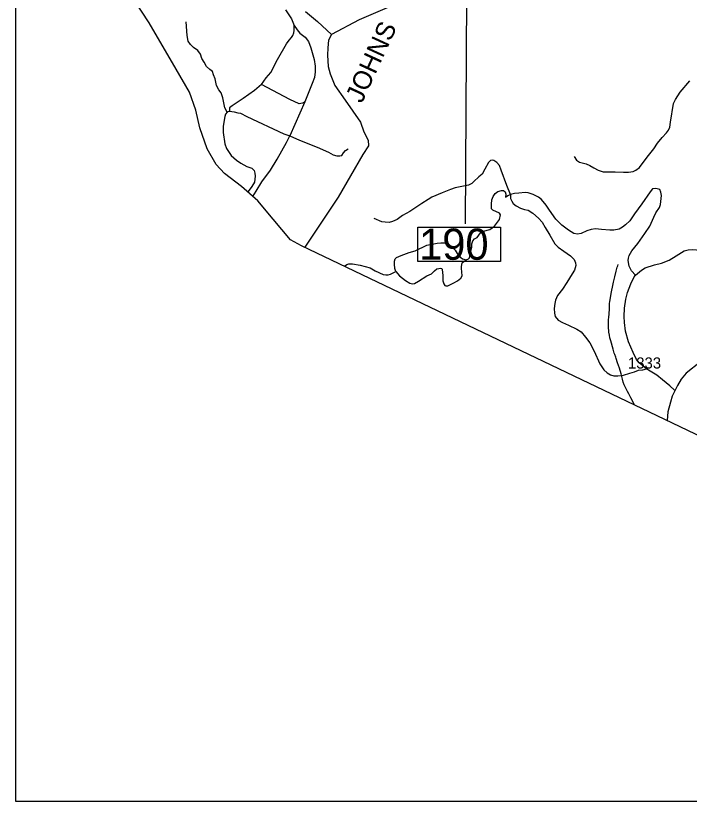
# Model space of a CAD drawing. Extents: x 1159738 to 1321356, y 736314 to 882035.
# Drawn here: x 1194108 to 1201667, y 778002 to 786937 of the extents above; entities that cross this region are included whole.
import ezdxf

# ---------------------------------------------------------------- set-up
doc = ezdxf.new("R2010")
doc.units = 0
for name, color, linetype in [('Exist Boundary Political CountyLine', 7, 'Continuous'), ('Exist Hydrographic Creek Single Shore', 7, 'Continuous'), ('Exist Hydrographic Misc Water Feature', 7, 'Continuous'), ('Exist Hydrographic River Shore Label', 7, 'Continuous'), ('Exist Road Non-System Type 51', 7, 'Continuous'), ('Exist Road Secondary Structure Standard Bridge Number Label', 7, 'Continuous'), ('Exist Road Secondary Type 51 Attributed', 7, 'Continuous'), ('Exist Road Secondary Type 51 Number Label', 7, 'Continuous'), ('Map Preparation Inset Cut Line', 7, 'Continuous')]:
    doc.layers.add(name, color=color, linetype=linetype)

msp = doc.modelspace()

# ---------------------------------------------------------------- linework, layer by layer
at = {"layer": 'Exist Boundary Political CountyLine'}
for points in [[(1197314.8, 784354.4), (1197192.2, 784421.4), (1196997.9, 784653.6), (1196823.8, 784860.6), (1196640.2, 785018.6), (1196451.9, 785167.4), (1196355.7, 785268), (1196257.2, 785443.9), (1196173.7, 785681.1), (1196129.3, 785876.5), (1196055.2, 786081.5), (1195906.3, 786340.6), (1195602.3, 786860.3), (1195338.2, 787267.6)], [(1221685.3, 768579.9), (1219889.4, 769468.2), (1217945.2, 774091.7), (1206156.9, 780126), (1197314.8, 784354.4)]]:
    msp.add_lwpolyline(points, dxfattribs=at)
at = {"layer": 'Exist Hydrographic Creek Single Shore'}
for points in [[(1199116.5, 787725.2), (1199099.6, 787584.1), (1199032.6, 787457.5), (1198958.2, 787342.2), (1198850.4, 787286.3), (1198511.9, 787133.7), (1197961.5, 786891.8), (1197650.1, 786728.9)], [(1197360.1, 786987.5), (1197493.6, 786874.7), (1197650.1, 786728.9)], [(1197650.1, 786728.9), (1197618.9, 786665.6), (1197609.6, 786580), (1197607.8, 786496.3), (1197613.3, 786367.9), (1197637.5, 786287.9), (1197689.6, 786153.9), (1197804.9, 785990.1), (1197977.8, 785742.6), (1198015, 785634.7), (1198063.4, 785541.6), (1198067.1, 785478.4), (1198003.9, 785381.6), (1197724.9, 784901.5), (1197350.5, 784337.3)]]:
    msp.add_lwpolyline(points, dxfattribs=at)
at = {"layer": 'Exist Hydrographic Misc Water Feature'}
msp.add_lwpolyline([(1201051.7, 782567.4), (1201049.6, 782573.9), (1201042.6, 782588.9), (1201014.5, 782647.1), (1200991.1, 782690), (1200974, 782717.6), (1200946.2, 782777), (1200939.3, 782792), (1200927.1, 782822.3), (1200920.2, 782853.9), (1200913.2, 782885.6), (1200904.3, 782916.5), (1200886.2, 782978.7), (1200865.1, 783040.3), (1200848.9, 783086.2), (1200843.1, 783101.4), (1200832.9, 783132.1), (1200827.9, 783147.4), (1200815.1, 783193.6), (1200788.5, 783287.4), (1200779, 783318.3), (1200772.3, 783349.9), (1200767.5, 783381.9), (1200761.4, 783446), (1200762, 783478.9), (1200762.3, 783495.3), (1200762.9, 783511.7), (1200763.5, 783528.1), (1200764.3, 783544.5), (1200765, 783560.9), (1200768.6, 783576.9), (1200770.7, 783593), (1200771.4, 783609.4), (1200771.8, 783625.8), (1200772.1, 783642.2), (1200772.4, 783658.6), (1200772.8, 783675), (1200773.7, 783707.9), (1200779.2, 783723), (1200794, 783818.1), (1200814.4, 783928.4), (1200817.6, 783944.2), (1200834.2, 784005.8), (1200850.2, 784067.1), (1200861.5, 784113.6), (1200866.7, 784129.1), (1200872.5, 784144.2)], dxfattribs=at)
at = {"layer": 'Exist Road Non-System Type 51'}
msp.add_line((1196504.7, 785867.5), (1196478.3, 785856), dxfattribs=at)
for points in [[(1197135.6, 787004.1), (1197200.8, 786905.6), (1197232.1, 786830.6)], [(1196478.3, 785856), (1196452, 785905.4), (1196432.2, 786015.9), (1196410.8, 786073.5), (1196387.7, 786104.9), (1196359.7, 786154.3), (1196346.6, 786230.1), (1196326.8, 786274.6), (1196313.6, 786312.6), (1196284, 786334), (1196247.7, 786368.6), (1196221.4, 786416.4), (1196195.3, 786460.1), (1196178.9, 786507.9), (1196149.2, 786547.4), (1196101.4, 786580.4), (1196068.5, 786616.7), (1196042.1, 786654.6), (1196029, 786715.6), (1196020.7, 786870.5)], [(1196864.8, 786165.8), (1196919.2, 786241.6), (1196968.6, 786302.6), (1197044.4, 786446), (1197148.1, 786624.7), (1197176.1, 786664.2), (1197202.4, 786695.5), (1197217.3, 786715.3), (1197227.1, 786748.3), (1197233.7, 786773), (1197232.1, 786830.6)], [(1197232.1, 786830.6), (1197265, 786779.5), (1197296.3, 786744.9), (1197355.6, 786698.8), (1197391.9, 786651), (1197419.9, 786578.4), (1197456.1, 786448.2), (1197469.3, 786372.4), (1197469.3, 786309.8), (1197459.4, 786243.8), (1197433.1, 786179.5), (1197354, 785973), (1197184.4, 785590.6)], [(1196864.8, 786165.8), (1196788, 786098.3), (1196659.5, 786007.6), (1196536, 785928.5), (1196508, 785903.8), (1196504.7, 785867.5)], [(1197354, 785973), (1197326, 785956.5), (1197289.8, 785949.9), (1197184.4, 785999.3), (1196864.8, 786165.8)], [(1200377.7, 785358), (1200403.6, 785316.8), (1200435.6, 785293.9), (1200510.3, 785274.1), (1200551.4, 785255.8), (1200598.6, 785229.9), (1200647.4, 785202.5), (1200702.2, 785185.7), (1200837.8, 785184.2), (1200929.2, 785181.1), (1200988.6, 785181.1), (1201040.4, 785187.2), (1201069.4, 785202.5), (1201109, 785234.5), (1201197.4, 785348.8), (1201270.5, 785441.8), (1201311.6, 785505.8), (1201364.9, 785571.4), (1201413.7, 785621.7), (1201437.4, 785651.5), (1201451.1, 785688.1), (1201458.7, 785744.5), (1201492.2, 785953.4), (1201516.6, 785997.6), (1201565.4, 786079.9), (1201676.6, 786208)], [(1196478.3, 785856), (1196462.2, 785833.6), (1196455.6, 785805.5), (1196434.2, 785698.4), (1196434.2, 785627.5), (1196452.3, 785498.9), (1196473.7, 785446.2), (1196524.8, 785368.7), (1196585.7, 785316), (1196633.5, 785281.4), (1196701, 785246.7), (1196755.4, 785225.3), (1196781.7, 785200.6), (1196791.6, 785169.3), (1196796.1, 785137), (1196787.8, 785069.4), (1196756.6, 785020), (1196715.4, 784962.3)], [(1196504.7, 785867.5), (1196557.4, 785857.6), (1196598.6, 785849.4), (1196631.5, 785842.8), (1196699.1, 785808.2), (1197117.4, 785613.7), (1197184.4, 785590.6)], [(1196769.7, 784909.5), (1196806, 784968.9), (1196868.6, 785072.7), (1196965.7, 785204.6), (1197041.5, 785326.6), (1197145.3, 785514.5), (1197184.4, 785590.6)], [(1197184.4, 785590.6), (1197291.5, 785541.7), (1197492.5, 785461), (1197619.3, 785404.9), (1197668.7, 785376.9), (1197713.2, 785363.7), (1197746.1, 785363.7), (1197765.9, 785367), (1197787.3, 785398.3), (1197810.4, 785424.7), (1197840, 785442.8)], [(1199660.2, 784929.8), (1199620.6, 785030.3), (1199556.4, 785203.4), (1199536.6, 785257.8), (1199508.6, 785290.7), (1199475.7, 785313.8), (1199460.9, 785317.1), (1199437.8, 785313.8), (1199414.7, 785290.7), (1199375.2, 785213.3), (1199343.9, 785157.2), (1199307.7, 785127.6), (1199251.7, 785078.1), (1199227, 785055), (1199189.1, 785033.6), (1199116.6, 785022.1), (1199040.8, 785003.9), (1198986.5, 784987.5), (1198894.2, 784947.9), (1198779.9, 784898.8), (1198738.7, 784872.4), (1198667.8, 784829.5), (1198598.7, 784785), (1198532.8, 784738.9), (1198450.4, 784696), (1198387.8, 784649.9), (1198336.8, 784626.8), (1198300.5, 784616.9), (1198256.1, 784618.6), (1198218.2, 784623.5), (1198129.2, 784661.4)], [(1201064.5, 784023.1), (1201020.3, 784074.4), (1200995.8, 784125.5), (1200984.4, 784189.7), (1200986.3, 784216.2), (1200993.9, 784246.5), (1201024.1, 784297.5), (1201092.1, 784380.7), (1201169.6, 784492.3), (1201228.2, 784575.4), (1201269.7, 784677.5), (1201292.4, 784722.9), (1201335.9, 784785.3), (1201347.2, 784819.3), (1201356.6, 784917.6), (1201351, 784955.5), (1201337.7, 784985.7), (1201309.4, 784995.2), (1201284.8, 784998.9), (1201258.4, 784995.2), (1201230.1, 784959.2), (1201137.5, 784826.9), (1201054.3, 784711.6), (1201003.3, 784634.1), (1200954.2, 784588.7), (1200918.3, 784562.2), (1200880.5, 784539.5), (1200822, 784530.1), (1200776.6, 784530.1), (1200683.6, 784535.9), (1200617.4, 784543.5), (1200566.4, 784537.8), (1200517.3, 784520.8), (1200456.9, 784490.5), (1200415.3, 784483), (1200371.8, 784492.4), (1200313.3, 784528.4), (1200239.6, 784585.1), (1200169.7, 784655), (1200099.8, 784755.2), (1200063.9, 784810.1), (1200011.3, 784875.7), (1199977.3, 784900.3), (1199916.8, 784928.7), (1199862, 784947.6), (1199826.2, 784951.4), (1199754.4, 784945.7), (1199705.2, 784941.9), (1199660.2, 784929.8)], [(1199165.3, 784197.8), (1199191, 784207.2), (1199202.5, 784217.1), (1199212.4, 784273.1), (1199227.2, 784339), (1199228.9, 784377), (1199237.1, 784411.6), (1199256.9, 784431.3), (1199288.2, 784447.8), (1199326.1, 784500.6), (1199359, 784518.7), (1199429.9, 784538.5), (1199482.6, 784573.1), (1199536.9, 784648.9), (1199550.1, 784701.7), (1199536.9, 784719.8), (1199462.8, 784754.4), (1199449.6, 784770.9), (1199449.6, 784820.4), (1199451, 784870.4), (1199465.8, 784906.7), (1199490.5, 784941.3), (1199520.2, 784962.7), (1199561.3, 784974.3), (1199584.4, 784974.3), (1199602.5, 784961.1), (1199610.8, 784933.1), (1199607.5, 784901.7), (1199633.8, 784919.9), (1199660.2, 784929.8)], [(1199660.2, 784929.8), (1199663.7, 784885.2), (1199675, 784856.8), (1199692, 784828.5), (1199726, 784803.9), (1199775.1, 784775.5), (1199818.6, 784760.4), (1199862, 784752.8), (1199911.2, 784720.7), (1199977.3, 784664), (1200017, 784620.5), (1200052.9, 784558.1), (1200102, 784474.9), (1200158.7, 784374.7), (1200196.5, 784336.9), (1200262.6, 784293.4), (1200334.2, 784243), (1200377.7, 784201.4), (1200390.9, 784161.7), (1200396.6, 784133.3), (1200381.5, 784080.4), (1200355, 784038.8), (1200292.7, 783940.5), (1200247.3, 783866.7), (1200190.6, 783796.8), (1200166.1, 783744.5), (1200158.5, 783704.8), (1200151, 783650), (1200154.8, 783597), (1200162.3, 783561.1), (1200198.2, 783519.5), (1200245.4, 783493), (1200313.5, 783460.9), (1200407.4, 783418.7), (1200456.6, 783386.5), (1200505.7, 783327.9), (1200551, 783263.6), (1200600.2, 783169.1), (1200664.4, 783027.3), (1200709.7, 782959.2), (1200745.6, 782927.1), (1200783.4, 782902.5), (1200823.1, 782893.1), (1200868.4, 782891.2), (1200930.8, 782898.7), (1201002.6, 782921.4), (1201055.5, 782938.4), (1201098.9, 782955.5), (1201146.2, 782959.2), (1201190.9, 782970.8)], [(1198373.4, 784065.9), (1198364.8, 784100.5), (1198359.8, 784148.3), (1198359.8, 784181.3), (1198368, 784209.3), (1198382.9, 784222.5), (1198433.9, 784245.6), (1198522.9, 784280.2), (1198592.1, 784298.3), (1198720.5, 784361), (1198837.5, 784382.4), (1198878.7, 784389), (1198923.1, 784385.7), (1198954.4, 784374.2), (1199005.5, 784337.9), (1199040.1, 784304.9), (1199073, 784250.5), (1199102.7, 784220.9), (1199124.1, 784209.3), (1199165.3, 784197.8)], [(1201064.5, 784023.1), (1201132.5, 784079.1), (1201175.9, 784105.5), (1201279.9, 784141.5), (1201359.2, 784158.5), (1201442.3, 784192.5), (1201521.7, 784241.7), (1201612.4, 784298.4), (1201655.8, 784309.7), (1201706.8, 784311.6), (1201752.2, 784309.7), (1201803.2, 784298.4), (1201852.3, 784273.8)], [(1198373.4, 784065.9), (1198414.6, 784018.1), (1198482.2, 783963.7), (1198531.6, 783934), (1198559.6, 783927.4), (1198584.3, 783930.7), (1198628.8, 783957.1), (1198722.6, 784018.1), (1198773.7, 784037.9), (1198809.9, 784072.5), (1198834.7, 784093.9), (1198856.1, 784098.9), (1198870.9, 784102.2), (1198889, 784098.9), (1198894, 784087.3), (1198900.5, 784021.4), (1198903.8, 783962.1), (1198913.7, 783927.4), (1198925.2, 783909.3), (1198936.8, 783904.4), (1198959.8, 783904.4), (1199025.3, 783937.4), (1199068.1, 783960.4), (1199102.7, 783991.7), (1199117.5, 784014.8), (1199114.2, 784062.6), (1199110.9, 784098.9), (1199110.9, 784120.3), (1199120.8, 784161.5), (1199142.2, 784183), (1199165.3, 784197.8)], [(1197798.6, 784125.2), (1197823.3, 784145), (1197846.4, 784150), (1197889.2, 784150), (1197973.2, 784136.8), (1198085.2, 784105.5), (1198142.8, 784070.8), (1198233.4, 784031.3), (1198261.4, 784026.3), (1198289.4, 784028), (1198315.8, 784036.2), (1198373.4, 784065.9)], [(1201190.9, 782970.8), (1201107.7, 783037), (1201075.6, 783074.8), (1201037.8, 783154.2), (1200986.8, 783273.3), (1200954.7, 783396.2), (1200943.4, 783490.8), (1200937.7, 783560.7), (1200941.7, 783652.5), (1200958.7, 783752.7), (1200977.6, 783830.2), (1201013.5, 783926.6), (1201051.3, 784004.2), (1201064.5, 784023.1)], [(1201504.5, 782732.6), (1201451.6, 782779.9), (1201368.5, 782847.9), (1201304.2, 782900.9), (1201211.6, 782955.7), (1201190.9, 782970.8)]]:
    msp.add_lwpolyline(points, dxfattribs=at)
at = {"layer": 'Exist Road Secondary Structure Standard Bridge Number Label'}
msp.add_line((1199169.8, 787643.4), (1199152.3, 784599.8), dxfattribs=at)
msp.add_lwpolyline([(1198622.4, 784561.5), (1199551.4, 784561.5), (1199551.4, 784177.4), (1198622.4, 784177.4)], close=True, dxfattribs=at)
at = {"layer": 'Exist Road Secondary Type 51 Attributed'}
msp.add_lwpolyline([(1201795.1, 783049.9), (1201635.1, 782922.9), (1201580.3, 782855.2), (1201536.1, 782784.8), (1201476.8, 782664.7), (1201458.9, 782597), (1201429.9, 782486.6), (1201421.8, 782390.4)], dxfattribs=at)
at = {"layer": 'Map Preparation Inset Cut Line'}
msp.add_lwpolyline([(1213574.8, 778108.9), (1194107.7, 778108.9), (1194107.7, 805981), (1213574.8, 805981)], close=True, dxfattribs=at)

# ---------------------------------------------------------------- texts
at = {"layer": 'Exist Hydrographic River Shore Label'}
msp.add_text('JOHNS', height=210, rotation=65.28703, dxfattribs=at).set_placement((1197992.3, 785946.1))
at = {"layer": 'Exist Road Secondary Structure Standard Bridge Number Label'}
msp.add_text('190', height=350, dxfattribs=at).set_placement((1198635, 784197.1))
at = {"layer": 'Exist Road Secondary Type 51 Number Label'}
msp.add_text('1333', height=125, dxfattribs=at).set_placement((1200981.2, 782974.7))

doc.saveas('drawing.dxf')
